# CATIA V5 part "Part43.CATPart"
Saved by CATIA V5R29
Part number: threaded rod
Revision: ANY
Definition: UNKNOWN
Nomenclature: threaded rod
Source: Unknown
Bounding box of the stored display mesh (mm): x -11.75 to 11.75, y 0 to 240, z -11.75 to 11.75
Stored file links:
  C:\Users\Administrator\Desktop\프로젝트\Gripper\Part43.CATPart
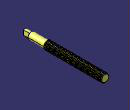
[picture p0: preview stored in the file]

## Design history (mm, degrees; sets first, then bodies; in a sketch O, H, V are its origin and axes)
Body1 "Cut-Extrude2" (main body)
  Solid1: solid without history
